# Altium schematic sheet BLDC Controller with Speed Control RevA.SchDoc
size 457 x 330 mm
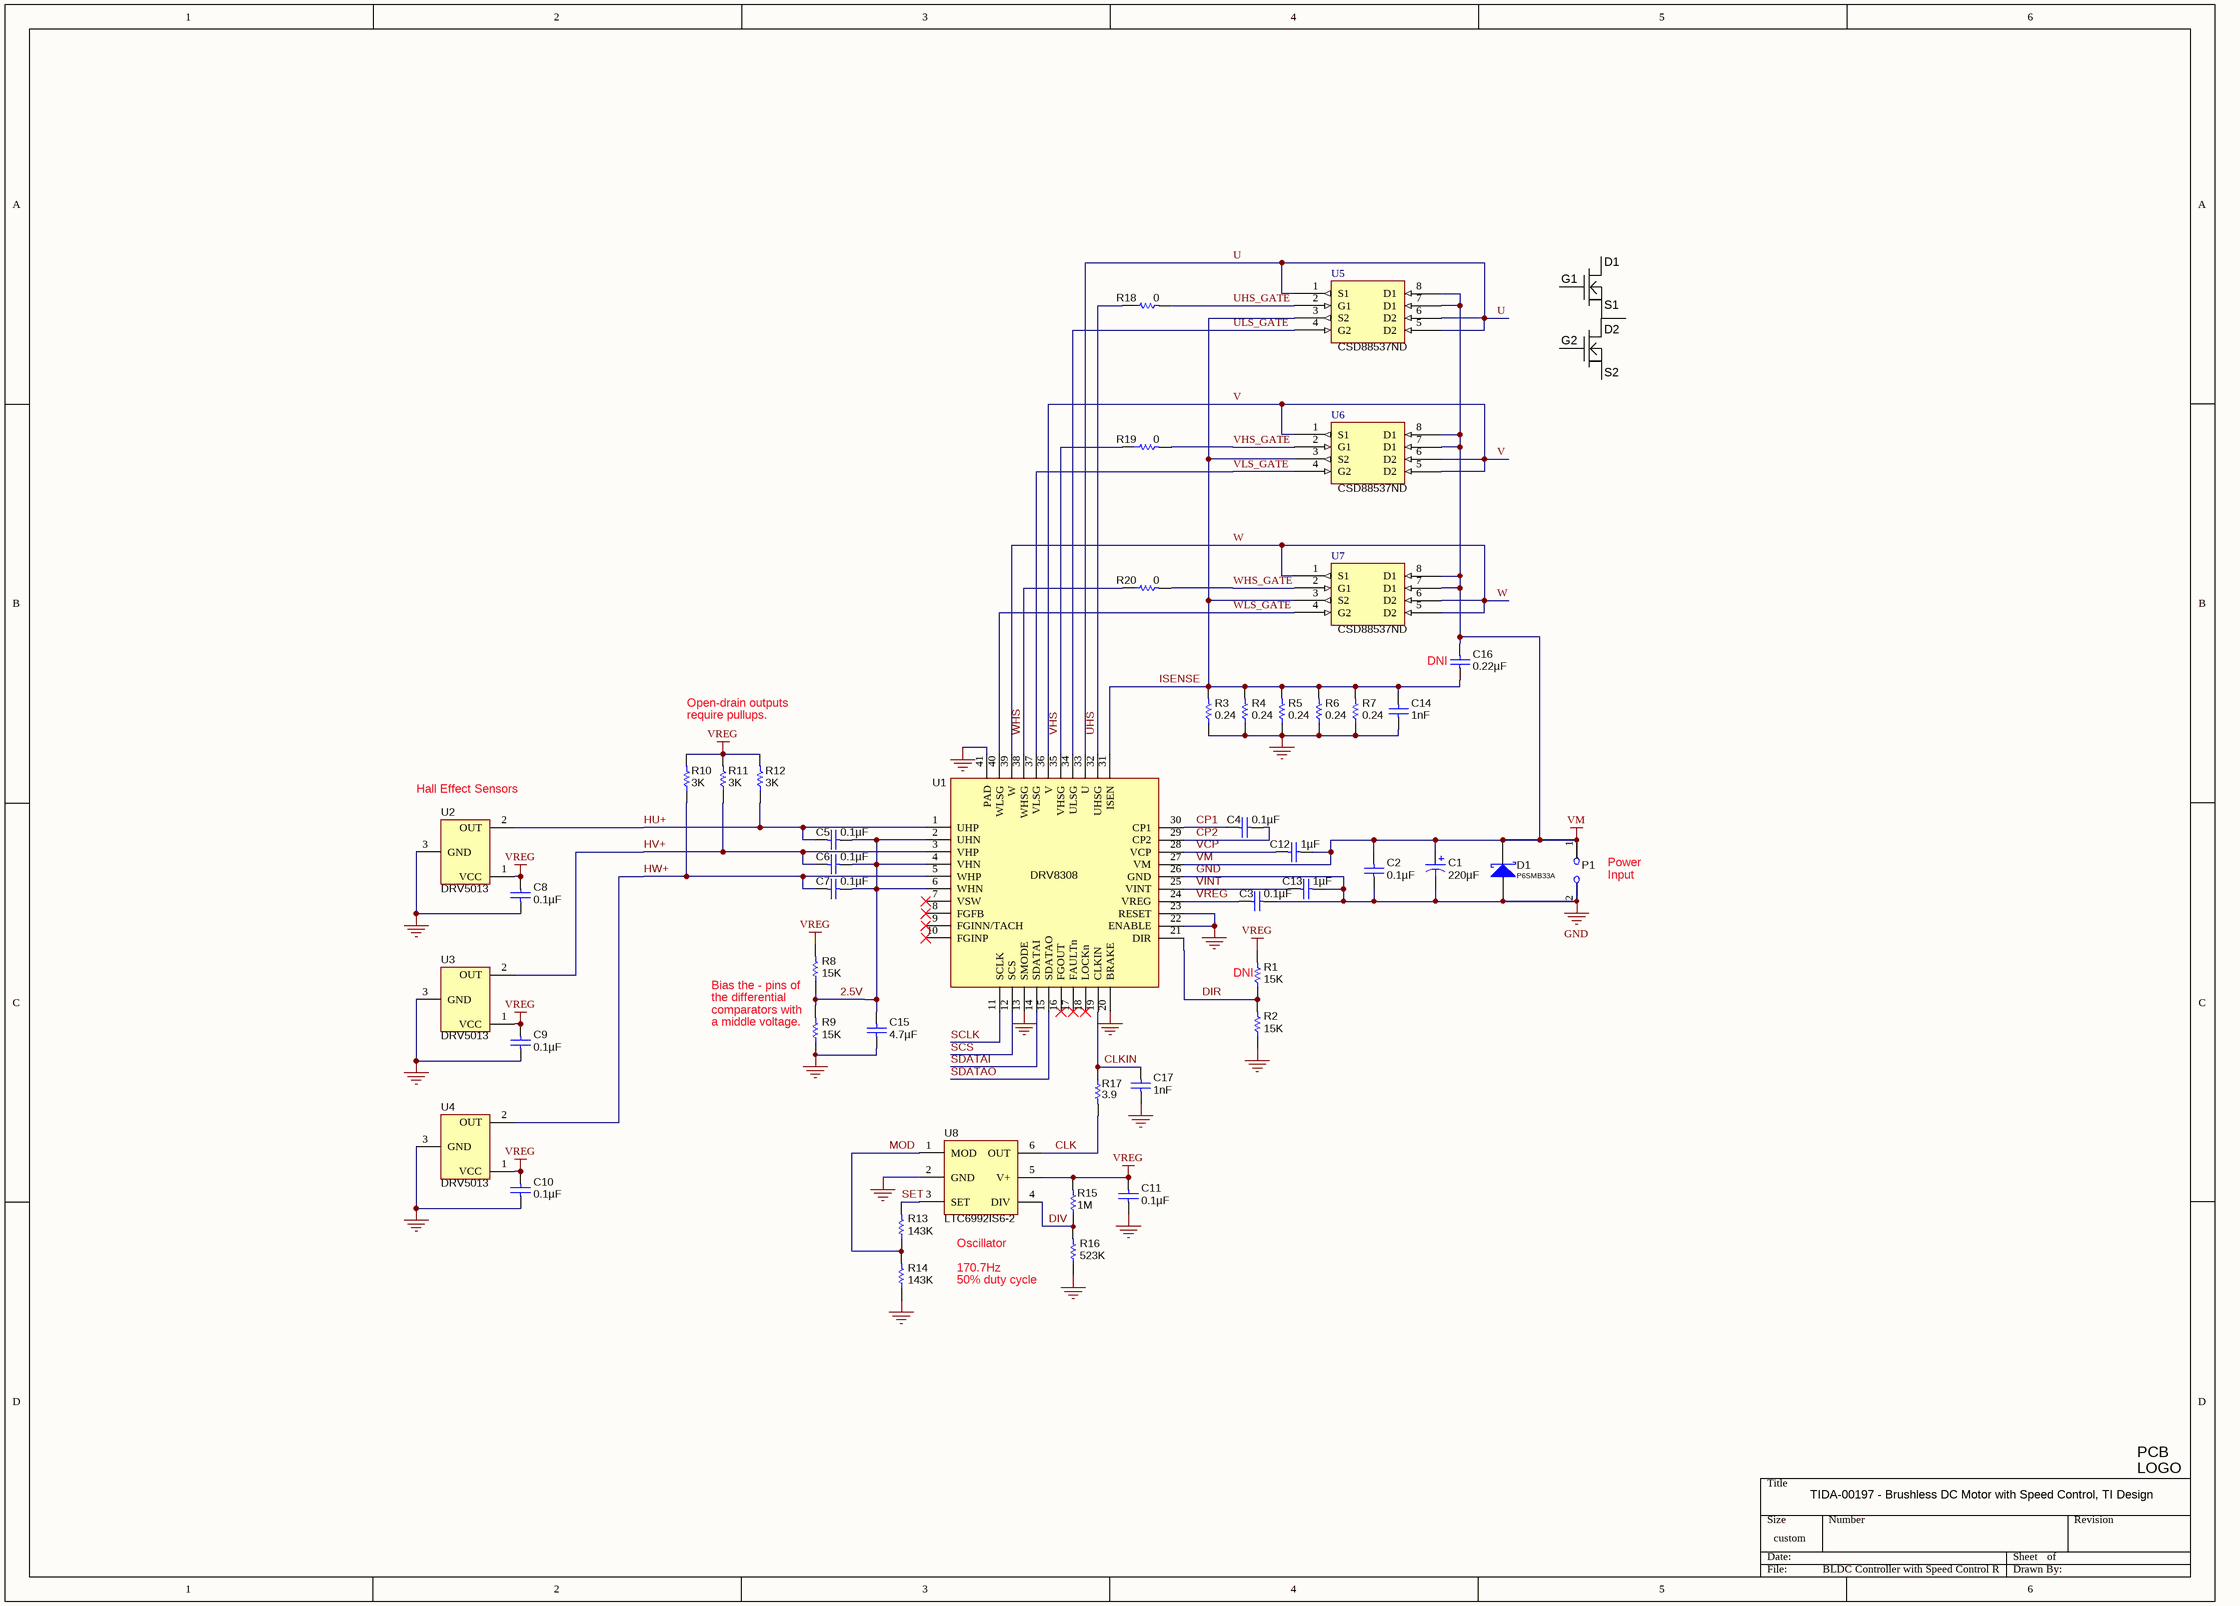
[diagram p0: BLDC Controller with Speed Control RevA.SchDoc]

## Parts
C1  value 220µF  [SM_RADIAL_G]
C2  value 0.1µF  [0603L]
C3  value 0.1µF  [0603L]
C4  value 0.1µF  [0603L]
C5  value 0.1µF  [0603L]
C6  value 0.1µF  [0603L]
C7  value 0.1µF  [0603L]
C8  value 0.1µF  [0603L]
C9  value 0.1µF  [0603L]
C10  value 0.1µF  [0603L]
C11  value 0.1µF  [0603L]
C12  value 1µF  [0603L]
C13  value 1µF  [0603L]
C14  value 1nF  [0603L]
C15  value 4.7µF  [0603L]
C16  value 0.22µF  [0603L]
C17  value 1nF  [0603L]
D1  MFG Part Number: P6SMB33A  [SMB]
LOGO  Texas Instruments  [TI_Symbol_Overlay_Medium]  (value not drawn)  (no BOM)
P1  JUMPER_2X100MIL  [2PIN HEADER]  (value not drawn)
R1  value 15K  [0603L]
R2  value 15K  [0603L]
R3  value 0.24  [0805L]
R4  value 0.24  [0805L]
R5  value 0.24  [0805L]
R6  value 0.24  [0805L]
R7  value 0.24  [0805L]
R8  value 15K  [0603L]
R9  value 15K  [0603L]
R10  value 3K  [0603L]
R11  value 3K  [0603L]
R12  value 3K  [0603L]
R13  value 143K  [0603L]
R14  value 143K  [0603L]
R15  value 1M  [0805L]
R16  value 523K  [0603L]
R17  value 3.9  [0603L]
R18  value 0  [0603L]
R19  value 0  [0603L]
R20  value 0  [0603L]
U1  DRV8308  [RHA0040A]
U2  DRV5013  [DBZ0003A_N]
U3  DRV5013  [DBZ0003A_N]
U4  DRV5013  [DBZ0003A_N]
U5  CSD88537ND  [SO-8_N]
U6  CSD88537ND  [SO-8_N]
U7  CSD88537ND  [SO-8_N]
U8  LTC6992IS6-2  [SOT23-6]

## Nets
GND: C1.2(-) C2.2 C3.2 C8.2 C9.2 C10.2 C11.2 C13.2 C14.2 C15.2 C17.2 D1.2(A) P1.2 R2.1 R3.1 R4.1 R5.1 R6.1 R7.1 R9.1 R14.1 R16.1 U1.13(SMODE) U1.20(BRAKE) U1.22(ENABLE) U1.23(RESET) U1.26(GND) U1.41(PAD) U2.3(GND) U3.3(GND) U4.3(GND) U8.2(GND)
VM: C1.1(+) C2.1 C12.2 C16.1 D1.1(K) P1.1 U1.27(VM) U5.7(D1) U5.8(D1) U6.7(D1) U6.8(D1) U7.7(D1) U7.8(D1)
VREG: C3.1 C8.1 C9.1 C10.1 C11.1 R1.2 R8.2 R10.2 R11.2 R12.2 R15.2 U1.24(VREG) U2.1(VCC) U3.1(VCC) U4.1(VCC) U8.5(V+)
2.5V: C5.2 C6.2 C7.2 C15.1 R8.1 R9.2 U1.2(UHN) U1.4(VHN) U1.6(WHN)
CLK: R17.2 U8.6(OUT)
CLKIN: C17.1 R17.1 U1.19(CLKIN)
CP1: C4.1 U1.30(CP1)
CP2: C4.2 U1.29(CP2)
DIR: R1.1 R2.2 U1.21(DIR)
DIV: R15.1 R16.2 U8.4(DIV)
HU+: C5.1 R12.1 U1.1(UHP) U2.2(OUT)
HV+: C6.1 R11.1 U1.3(VHP) U3.2(OUT)
HW+: C7.1 R10.1 U1.5(WHP) U4.2(OUT)
ISENSE: C14.1 C16.2 R3.2 R4.2 R5.2 R6.2 R7.2 U1.31(ISEN) U5.3(S2) U6.3(S2) U7.3(S2)
MOD: R13.1 R14.2 U8.1(MOD)
SCLK: U1.11(SCLK)
SCS: U1.12(SCS)
SDATAI: U1.14(SDATAI)
SDATAO: U1.15(SDATAO)
SET: R13.2 U8.3(SET)
U: U1.33(U) U5.1(S1) U5.5(D2) U5.6(D2)
UHS: R18.1 U1.32(UHSG)
UHS_GATE: R18.2 U5.2(G1)
ULS_GATE: U1.34(ULSG) U5.4(G2)
V: U1.36(V) U6.1(S1) U6.5(D2) U6.6(D2)
VCP: C12.1 U1.28(VCP)
VHS: R19.1 U1.35(VHSG)
VHS_GATE: R19.2 U6.2(G1)
VINT: C13.1 U1.25(VINT)
VLS_GATE: U1.37(VLSG) U6.4(G2)
W: U1.39(W) U7.1(S1) U7.5(D2) U7.6(D2)
WHS: R20.1 U1.38(WHSG)
WHS_GATE: R20.2 U7.2(G1)
WLS_GATE: U1.40(WLSG) U7.4(G2)

Not connected (* = marked no-connect by the designer): U1 7(VSW)* 8(FGFB)* 9(FGINN/TACH)* 10(FGINP)* 16(FGOUT)* 17(FAULTn)* 18(LOCKn)*

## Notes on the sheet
- D1
- G1
- D2
- S1
- G2
- S2
- (near C16) DNI
- Open-drain outputs
- require pullups.
- (near U2) Hall Effect Sensors
- (near P1) Power
- (near P1) Input
- (near R8) Bias the - pins of
- the differential
- (near R9) comparators with
- (near R1) DNI
- (near R9) a middle voltage.
- Oscillator
- 170.7Hz
- (near R16) 50% duty cycle
- (near LOGO) TIDA-00197 - Brushless DC Motor with Speed Control, TI Design

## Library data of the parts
C1 = EEE-FC1H101P: Manufacturer: Nichicon; MFG Part Number: UWT1H221MNL1GS; Description: CAP ALUM 220UF 50V 20% SMD
C2-C11 = 0603YC104JAT2A: Manufacturer: Yageo; MFG Part Number: CC0603KRX7R9BB104; Description: CAP CER 0.1UF 50V 10% X7R 0603
C12 C13 = 0603YC104JAT2A: Manufacturer: Taiyo Yuden; MFG Part Number: UMK107BJ105KA-T; Description: CAP CER 1UF 50V 10% X5R 0603
C14 C17 = 0603YC104JAT2A: Manufacturer: Kemet; MFG Part Number: C0603C102K5RACTU; Description: CAP CER 1000PF 50V 10% X7R 0603
C15 = 0603YC104JAT2A: Manufacturer: Taiyo Yuden; MFG Part Number: JMK107BJ475KA-T; Description: CAP CER 4.7UF 6.3V 10% X5R 0603
C16 = 0603YC104JAT2A: Manufacturer: TDK; MFG Part Number: C1608X7R1H224K080AB; Description: CAP CER 0.22UF 50V 10% X7R 0603
D1 = 10BQ030TRPBF: Manufacturer: Littelfuse; Description: TVS DIODE 28.2VWM 45.7VC SMD
LOGO = TI_Logo: Texas Instrument Corporate Signature; SymbolCreator: a0412235
P1 = JUMPER_2X100MIL: Header, Male 2-pin, 100mil spacing,; Manufacturer: 3M; MFG Part Number: 929647-01-02-EU; Description: CONN HEADER 2POS STR .100" GOLD
R1 R2 R8 R9 = CRCW06031K00FKEA: Manufacturer: Yageo; MFG Part Number: RC0603FR-0715KL; Description: RES 15.0K OHM 1/10W 1% 0603 SMD
R3-R7 = CRCW08051K13FKEA: Manufacturer: TE Connectivity; MFG Part Number: RLP73N2AR24JTD; Description: RES 0.24 OHM 1/4W 5% 0805
R10-R12 = CRCW06031K00FKEA: Manufacturer: Yageo; MFG Part Number: RC0603JR-073KL; Description: RES 3.0K OHM 1/10W 5% 0603 SMD
R13 R14 = CRCW06031K00FKEA: Manufacturer: Yageo; MFG Part Number: RC0603FR-07143KL; Description: RES 143K OHM 1/10W 1% 0603 SMD
R15 = CRCW08051K00FKEA: Manufacturer: Panasonic; MFG Part Number: ERA-6AEB105V; Description: RES 1M OHM 1/8W .1% 0805 SMD
R16 = CRCW06031K00FKEA: Manufacturer: Yageo; MFG Part Number: RC0603FR-07523KL; Description: RES 523K OHM 1/10W 1% 0603 SMD
R17 = CRCW06031K00FKEA: Manufacturer: Yageo; MFG Part Number: RC0603FR-073R92L; Description: RES 3.92 OHM 1/10W 1% 0603 SMD
R18-R20 = CRCW06031K00FKEA: Manufacturer: Yageo; MFG Part Number: RC0603JR-070RL; Description: RES 0.0 OHM 1/10W JUMP 0603 SMD
U1 = DRV8308: Manufacturer: Texas Instruments; MFG Part Number: DRV8308RHAT; Description: BLDC MOTOR PREDRIVER
U2-U4 = DRV5xxxDBZ: Hall sensor; Manufacturer: Texas Instruments; MFG Part Number: DRV5013ADQDBZR
U5-U7 = FDS8949: MOSFET N-CH DUAL 30V 3.5A SOP8; Manufacturer: Texas Instruments; Description: MOSFET N-CH 60V DUAL 8SOIC
U8 = LTC6992-2: Manufacturer: Linear Technology; MFG Part Number: LTC6992IS6-2#TRMPBF; Description: IC OSC SILICON 1MHZ TSOT23-6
